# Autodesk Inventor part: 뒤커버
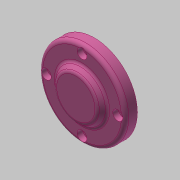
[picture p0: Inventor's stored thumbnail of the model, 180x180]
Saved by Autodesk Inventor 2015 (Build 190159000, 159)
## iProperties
Created: 2017-08
Part Number: 뒤커버
Material: 알루미늄 6061
Document SubType Name: Modeling
Designer: mduedu
Density: 2.71 g/cm^3
Appearance: 분홍색
Mass: 99.1139 g
Surface Area: 135.948 cm^2
Volume: 36.5734 cm^3
Author: mduedu
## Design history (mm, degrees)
sketch "스케치1"
  geometry: C1 r 35 at (0, 0); 1 further point
  constraints: 1 centre point, 1 coincident
  dimensions: "d0" = 70 diameter of C1
extrude "돌출1" new body sketch "스케치1" distance "d1" = 10; taper "d2" = 0 deg
sketch "스케치2"
  geometry: C1 r 21 at (0, 0); 1 further point
  constraints: 1 centre point, 1 coincident
  dimensions: "d3" = 42 diameter of C1
node "작업 평면1"
sketch "스케치3"
  geometry: C1 r 17 at (0, 0); 1 further point
  constraints: 1 centre point, 1 coincident
  dimensions: "d5" = 34 diameter of C1
feature "로프트1" sketch "스케치3" dims "d6" = 0, "d7" = 90 deg, "d8" = 0, "d9" = 90 deg
sketch "스케치4"
  geometry: C1 r 24 at (0, 0); 1 further point
  constraints: 1 centre point, 1 coincident
  dimensions: "d65" = 48 diameter of C1
extrude "돌출2" join sketch "스케치4" distance "d10" = 8; taper "d11" = 0 deg
hole "구멍1" diameter "d14" = 40; stored, may be unused: countersink angle "d18" = 90 deg, drill point angle "d20" = 0 deg; dims "d15" = 6, "d16" = 4, "d17" = 2, "d19" = 12, "d66" = 10, "d67" = 10
hole "구멍2" diameter "d23" = 34; stored, may be unused: countersink angle "d27" = 90 deg, drill point angle "d29" = 0 deg; dims "d24" = 6, "d25" = 4, "d26" = 2, "d28" = 6, "d62" = 10, "d63" = 10
chamfer "모따기1" distance "d39" = 1; stored, may be unused: second distance "d40" = 2, angle "d41" = 45 deg
fillet "모깎기1" dims "d42" = 0.3
fillet "모깎기2" dims "d43" = 3
sketch "스케치5" dims "d44" = 58
  geometry: 6 further points
  constraints: 2 vertical alignment, 1 coincident, 7 other
  dimensions: "d47" = 360 deg dimension on point (0, 0) point (0, 29) (derived)
sketch "스케치6" dims "d64" = 58 (derived)
  geometry: 6 further points
  constraints: 1 coincident, 1 vertical alignment, 6 other
hole "구멍4" sketch "스케치6" at (0, 29), (-29, 0), (29, 0), (0, -29) diameter "d49" = 4.5; stored, may be unused: countersink angle "d53" = 90 deg, drill point angle "d55" = 0 deg; dims "d50" = 6, "d51" = 8, "d52" = 4.6, "d54" = 8
fillet "모깎기3" dims "d56" = 3
fillet "모깎기4" dims "d57" = 3
fillet "모깎기5" dims "d58" = 3
node "솔리드1"
other parameters: "d4" = 5
